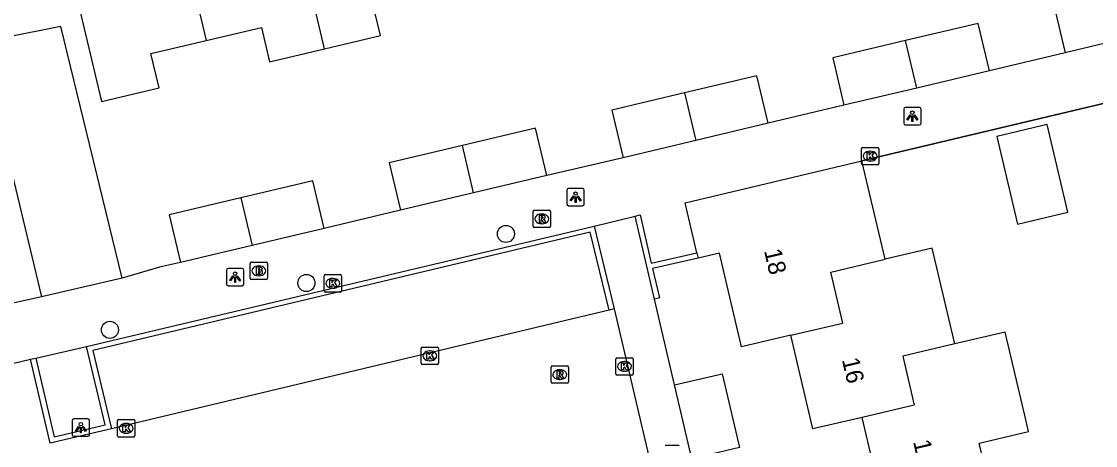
# Model space of a CAD drawing. Extents: x 158038 to 159242, y 380133 to 381214.
# Drawn here: x 158641.1 to 158702.8, y 380611 to 380635.3 of the extents above; entities that cross this region are included whole.
import ezdxf

# ---------------------------------------------------------------- set-up
doc = ezdxf.new("R2010")
doc.units = 0
for name, color, linetype in [('IMGEO_Boom', 7, 'Continuous'), ('IMGEO_Brandkraan', 7, 'Continuous'), ('IMGEO_Hek', 7, 'Continuous'), ('IMGEO_Kolk', 7, 'Continuous'), ('IMGEO_Lichtpunt', 7, 'Continuous'), ('IMGEO_Muur', 7, 'Continuous'), ('IMGEO_Pand', 7, 'Continuous'), ('IMGEO_Pand_nummerreeks', 7, 'Continuous'), ('IMGEO_Parkeervlak_open', 7, 'Continuous'), ('IMGEO_Rijbaan_lokaal_open', 7, 'Continuous'), ('IMGEO_Rioolput', 7, 'Continuous'), ('IMGEO_Voetpad_open', 7, 'Continuous')]:
    doc.layers.add(name, color=color, linetype=linetype)

msp = doc.modelspace()

# ---------------------------------------------------------------- linework, layer by layer
at = {"layer": 'IMGEO_Boom'}
for centre in [(158668.929, 380623.096), (158657.473, 380620.28), (158646.196, 380617.592)]:
    msp.add_circle(centre, 0.489, dxfattribs=at)
at = {"layer": 'IMGEO_Brandkraan'}
for p, q in [((158654.321, 380621.48), (158655.173, 380621.48)), ((158654.246, 380620.554), (158654.246, 380621.406)), ((158654.734, 380621.26), (158654.759, 380621.26)), ((158655.247, 380621.406), (158655.247, 380620.554)), ((158655.173, 380620.48), (158654.321, 380620.48)), ((158654.757, 380620.7), (158654.732, 380620.7))]:
    msp.add_line(p, q, dxfattribs=at)
for points in [[(158654.321, 380621.48), (158655.173, 380621.48)], [(158654.246, 380620.554), (158654.246, 380621.406)], [(158654.594, 380621.18), (158654.594, 380620.78), (158654.807, 380620.78)], [(158654.825, 380621.18), (158654.594, 380621.18)], [(158654.773, 380621.099), (158654.719, 380621.099), (158654.719, 380621.023)], [(158654.719, 380621.023), (158654.772, 380621.023)], [(158654.781, 380620.947), (158654.719, 380620.947), (158654.719, 380620.866)], [(158654.719, 380620.866), (158654.781, 380620.866)], [(158655.247, 380621.406), (158655.247, 380620.554)], [(158655.173, 380620.48), (158654.321, 380620.48)]]:
    msp.add_lwpolyline(points, dxfattribs=at)
for centre, radius, start, end in [((158654.323, 380621.404), 0.0765, 91.55205, 178.44795), ((158654.323, 380621.404), 0.0765, 91.55205, 178.44795), ((158655.171, 380621.404), 0.0765, 1.55205, 88.44795), ((158655.171, 380621.404), 0.0765, 1.55205, 88.44795), ((158654.774, 380621.061), 0.0379, 267.82845, 90.93552), ((158654.782, 380620.906), 0.0404, 269.87594, 90.50774), ((158654.829, 380621.035), 0.145, 59.4692, 91.53667), ((158654.854, 380621.082), 0.0922, 285.51372, 58.15012), ((158654.859, 380620.89), 0.105, 301.31148, 78.98903), ((158654.323, 380620.556), 0.0765, 181.55205, 268.44795), ((158654.323, 380620.556), 0.0765, 181.55205, 268.44795), ((158654.813, 380621.031), 0.251, 268.66757, 293.53466), ((158655.171, 380620.556), 0.0765, 271.55205, 358.44795), ((158655.171, 380620.556), 0.0765, 271.55205, 358.44795)]:
    msp.add_arc(centre, radius, start, end, dxfattribs=at)
for centre, major_axis, ratio, start_param, end_param in [((158654.733, 380620.98), (-0.387, 0.002), 0.722429, 4.712389, 7.853982), ((158654.758, 380620.98), (-0.39, 0.002), 0.717154, 1.570796, 4.712389)]:
    msp.add_ellipse(centre, major_axis=major_axis, ratio=ratio, start_param=start_param, end_param=end_param, dxfattribs=at)
at = {"layer": 'IMGEO_Hek'}
for points in [[(158646.891, 380620.567), (158643.384, 380635.009), (158640.207, 380634.374)], [(158649.038, 380621.183), (158646.891, 380620.567)]]:
    msp.add_lwpolyline(points, dxfattribs=at)
at = {"layer": 'IMGEO_Kolk'}
for p, q in [((158689.338, 380627.14), (158689.338, 380627.992)), ((158689.413, 380628.066), (158690.265, 380628.066)), ((158689.826, 380627.846), (158689.851, 380627.846)), ((158690.339, 380627.992), (158690.339, 380627.14)), ((158690.265, 380627.066), (158689.413, 380627.066)), ((158689.849, 380627.286), (158689.824, 380627.286)), ((158658.495, 380619.833), (158658.495, 380620.685)), ((158658.57, 380620.759), (158659.422, 380620.759)), ((158658.983, 380620.539), (158659.008, 380620.539)), ((158659.496, 380620.685), (158659.496, 380619.833)), ((158659.422, 380619.759), (158658.57, 380619.759)), ((158659.006, 380619.979), (158658.981, 380619.979)), ((158664.06, 380615.673), (158664.06, 380616.525)), ((158664.135, 380616.599), (158664.987, 380616.599)), ((158665.061, 380616.525), (158665.061, 380615.673)), ((158664.548, 380616.379), (158664.573, 380616.379)), ((158675.24, 380615.065), (158675.24, 380615.917)), ((158675.315, 380615.991), (158676.167, 380615.991)), ((158676.241, 380615.917), (158676.241, 380615.065)), ((158664.987, 380615.599), (158664.135, 380615.599)), ((158664.571, 380615.819), (158664.546, 380615.819)), ((158675.728, 380615.771), (158675.753, 380615.771)), ((158676.167, 380614.991), (158675.315, 380614.991)), ((158675.751, 380615.211), (158675.726, 380615.211)), ((158646.624, 380611.512), (158646.624, 380612.364)), ((158646.699, 380612.438), (158647.551, 380612.438)), ((158647.112, 380612.218), (158647.137, 380612.218)), ((158647.625, 380612.364), (158647.625, 380611.512)), ((158647.135, 380611.658), (158647.11, 380611.658)), ((158647.551, 380611.438), (158646.699, 380611.438))]:
    msp.add_line(p, q, dxfattribs=at)
for points in [[(158689.338, 380627.14), (158689.338, 380627.992)], [(158689.413, 380628.066), (158690.265, 380628.066)], [(158689.659, 380627.766), (158689.782, 380627.766), (158689.782, 380627.615), (158689.912, 380627.766), (158690.076, 380627.766), (158689.93, 380627.615), (158690.083, 380627.366), (158689.931, 380627.366), (158689.846, 380627.53), (158689.782, 380627.463), (158689.782, 380627.366), (158689.659, 380627.366), (158689.659, 380627.766)], [(158690.339, 380627.992), (158690.339, 380627.14)], [(158690.265, 380627.066), (158689.413, 380627.066)], [(158658.495, 380619.833), (158658.495, 380620.685)], [(158658.57, 380620.759), (158659.422, 380620.759)], [(158658.816, 380620.459), (158658.939, 380620.459), (158658.939, 380620.308), (158659.069, 380620.459), (158659.233, 380620.459), (158659.087, 380620.308), (158659.24, 380620.059), (158659.088, 380620.059), (158659.003, 380620.223), (158658.939, 380620.156), (158658.939, 380620.059), (158658.816, 380620.059), (158658.816, 380620.459)], [(158659.496, 380620.685), (158659.496, 380619.833)], [(158659.422, 380619.759), (158658.57, 380619.759)], [(158664.06, 380615.673), (158664.06, 380616.525)], [(158664.135, 380616.599), (158664.987, 380616.599)], [(158665.061, 380616.525), (158665.061, 380615.673)], [(158664.381, 380616.299), (158664.504, 380616.299), (158664.504, 380616.148), (158664.634, 380616.299), (158664.798, 380616.299), (158664.652, 380616.148), (158664.805, 380615.899), (158664.653, 380615.899), (158664.568, 380616.063), (158664.504, 380615.996), (158664.504, 380615.899), (158664.381, 380615.899), (158664.381, 380616.299)], [(158675.24, 380615.065), (158675.24, 380615.917)], [(158675.315, 380615.991), (158676.167, 380615.991)], [(158676.241, 380615.917), (158676.241, 380615.065)], [(158664.987, 380615.599), (158664.135, 380615.599)], [(158675.561, 380615.691), (158675.684, 380615.691), (158675.684, 380615.54), (158675.814, 380615.691), (158675.978, 380615.691), (158675.832, 380615.54), (158675.985, 380615.291), (158675.833, 380615.291), (158675.748, 380615.455), (158675.684, 380615.388), (158675.684, 380615.291), (158675.561, 380615.291), (158675.561, 380615.691)], [(158676.167, 380614.991), (158675.315, 380614.991)], [(158646.624, 380611.512), (158646.624, 380612.364)], [(158646.699, 380612.438), (158647.551, 380612.438)], [(158647.625, 380612.364), (158647.625, 380611.512)], [(158646.945, 380612.138), (158647.068, 380612.138), (158647.068, 380611.987), (158647.198, 380612.138), (158647.362, 380612.138), (158647.216, 380611.987), (158647.369, 380611.738), (158647.217, 380611.738), (158647.132, 380611.902), (158647.068, 380611.835), (158647.068, 380611.738), (158646.945, 380611.738), (158646.945, 380612.138)], [(158647.551, 380611.438), (158646.699, 380611.438)]]:
    msp.add_lwpolyline(points, dxfattribs=at)
for centre, start, end in [((158689.415, 380627.99), 91.55205, 178.44795), ((158689.415, 380627.99), 91.55205, 178.44795), ((158690.263, 380627.99), 1.55205, 88.44795), ((158690.263, 380627.99), 1.55205, 88.44795), ((158689.415, 380627.142), 181.55205, 268.44795), ((158689.415, 380627.142), 181.55205, 268.44795), ((158690.263, 380627.142), 271.55205, 358.44795), ((158690.263, 380627.142), 271.55205, 358.44795), ((158658.572, 380620.683), 91.55205, 178.44795), ((158658.572, 380620.683), 91.55205, 178.44795), ((158659.42, 380620.683), 1.55205, 88.44795), ((158659.42, 380620.683), 1.55205, 88.44795), ((158658.572, 380619.835), 181.55205, 268.44795), ((158658.572, 380619.835), 181.55205, 268.44795), ((158659.42, 380619.835), 271.55205, 358.44795), ((158659.42, 380619.835), 271.55205, 358.44795), ((158664.137, 380616.523), 91.55205, 178.44795), ((158664.137, 380616.523), 91.55205, 178.44795), ((158664.985, 380616.523), 1.55205, 88.44795), ((158664.985, 380616.523), 1.55205, 88.44795), ((158675.317, 380615.915), 91.55205, 178.44795), ((158675.317, 380615.915), 91.55205, 178.44795), ((158676.165, 380615.915), 1.55205, 88.44795), ((158676.165, 380615.915), 1.55205, 88.44795), ((158664.137, 380615.675), 181.55205, 268.44795), ((158664.137, 380615.675), 181.55205, 268.44795), ((158664.985, 380615.675), 271.55205, 358.44795), ((158664.985, 380615.675), 271.55205, 358.44795), ((158675.317, 380615.067), 181.55205, 268.44795), ((158675.317, 380615.067), 181.55205, 268.44795), ((158676.165, 380615.067), 271.55205, 358.44795), ((158676.165, 380615.067), 271.55205, 358.44795), ((158646.701, 380612.362), 91.55205, 178.44795), ((158646.701, 380612.362), 91.55205, 178.44795), ((158647.549, 380612.362), 1.55205, 88.44795), ((158647.549, 380612.362), 1.55205, 88.44795), ((158646.701, 380611.514), 181.55205, 268.44795), ((158646.701, 380611.514), 181.55205, 268.44795), ((158647.549, 380611.514), 271.55205, 358.44795), ((158647.549, 380611.514), 271.55205, 358.44795)]:
    msp.add_arc(centre, 0.0765, start, end, dxfattribs=at)
for centre, major_axis, ratio, start_param, end_param in [((158689.825, 380627.566), (-0.387, 0.002), 0.722429, 4.712389, 7.853982), ((158689.85, 380627.566), (-0.39, 0.002), 0.717154, 1.570796, 4.712389), ((158658.982, 380620.259), (-0.387, 0.002), 0.722429, 4.712389, 7.853982), ((158659.007, 380620.259), (-0.39, 0.002), 0.717154, 1.570796, 4.712389), ((158664.547, 380616.099), (-0.387, 0.002), 0.722429, 4.712389, 7.853982), ((158664.572, 380616.099), (-0.39, 0.002), 0.717154, 1.570796, 4.712389), ((158675.727, 380615.491), (-0.387, 0.002), 0.722429, 4.712389, 7.853982), ((158675.752, 380615.491), (-0.39, 0.002), 0.717154, 1.570796, 4.712389), ((158647.111, 380611.938), (-0.387, 0.002), 0.722429, 4.712389, 7.853982), ((158647.136, 380611.938), (-0.39, 0.002), 0.717154, 1.570796, 4.712389)]:
    msp.add_ellipse(centre, major_axis=major_axis, ratio=ratio, start_param=start_param, end_param=end_param, dxfattribs=at)
at = {"layer": 'IMGEO_Lichtpunt'}
for p, q in [((158691.765, 380630.263), (158691.765, 380629.456)), ((158691.765, 380630.263), (158691.765, 380629.456)), ((158692.667, 380630.358), (158691.859, 380630.358)), ((158692.667, 380630.358), (158691.859, 380630.358)), ((158692.761, 380629.456), (158692.761, 380630.263)), ((158692.761, 380629.456), (158692.761, 380630.263)), ((158691.859, 380629.362), (158692.667, 380629.362)), ((158691.859, 380629.362), (158692.667, 380629.362)), ((158672.43, 380625.615), (158672.43, 380624.808)), ((158672.43, 380625.615), (158672.43, 380624.808)), ((158673.332, 380625.71), (158672.524, 380625.71)), ((158673.332, 380625.71), (158672.524, 380625.71)), ((158673.426, 380624.808), (158673.426, 380625.615)), ((158673.426, 380624.808), (158673.426, 380625.615)), ((158672.524, 380624.714), (158673.332, 380624.714)), ((158672.524, 380624.714), (158673.332, 380624.714)), ((158652.883, 380621.022), (158652.883, 380620.215)), ((158652.883, 380621.022), (158652.883, 380620.215)), ((158653.785, 380621.117), (158652.977, 380621.117)), ((158653.785, 380621.117), (158652.977, 380621.117)), ((158653.879, 380620.215), (158653.879, 380621.022)), ((158653.879, 380620.215), (158653.879, 380621.022)), ((158652.977, 380620.121), (158653.785, 380620.121)), ((158652.977, 380620.121), (158653.785, 380620.121)), ((158644.026, 380612.38), (158644.026, 380611.573)), ((158644.026, 380612.38), (158644.026, 380611.573)), ((158644.928, 380612.475), (158644.12, 380612.475)), ((158644.928, 380612.475), (158644.12, 380612.475)), ((158645.022, 380611.573), (158645.022, 380612.38)), ((158645.022, 380611.573), (158645.022, 380612.38)), ((158644.12, 380611.479), (158644.928, 380611.479)), ((158644.12, 380611.479), (158644.928, 380611.479)), ((158678.881, 380610.95), (158678.073, 380610.95)), ((158678.881, 380610.95), (158678.073, 380610.95))]:
    msp.add_line(p, q, dxfattribs=at)
for points in [[(158692.139, 380629.927), (158692.178, 380629.899), (158691.99, 380629.637), (158691.952, 380629.664), (158692.139, 380629.927)], [(158692.241, 380629.879), (158692.288, 380629.879), (158692.288, 380629.557), (158692.241, 380629.557), (158692.241, 380629.879)], [(158692.351, 380629.899), (158692.389, 380629.926), (158692.576, 380629.664), (158692.537, 380629.636), (158692.351, 380629.899)], [(158672.804, 380625.279), (158672.843, 380625.251), (158672.655, 380624.989), (158672.617, 380625.016), (158672.804, 380625.279)], [(158672.906, 380625.231), (158672.953, 380625.231), (158672.953, 380624.909), (158672.906, 380624.909), (158672.906, 380625.231)], [(158673.016, 380625.251), (158673.054, 380625.278), (158673.241, 380625.016), (158673.202, 380624.988), (158673.016, 380625.251)], [(158653.257, 380620.686), (158653.296, 380620.658), (158653.108, 380620.396), (158653.07, 380620.423), (158653.257, 380620.686)], [(158653.359, 380620.638), (158653.406, 380620.638), (158653.406, 380620.316), (158653.359, 380620.316), (158653.359, 380620.638)], [(158653.469, 380620.658), (158653.507, 380620.685), (158653.694, 380620.423), (158653.655, 380620.395), (158653.469, 380620.658)], [(158644.4, 380612.044), (158644.439, 380612.016), (158644.251, 380611.754), (158644.213, 380611.781), (158644.4, 380612.044)], [(158644.502, 380611.996), (158644.549, 380611.996), (158644.549, 380611.674), (158644.502, 380611.674), (158644.502, 380611.996)], [(158644.612, 380612.016), (158644.65, 380612.043), (158644.837, 380611.781), (158644.798, 380611.753), (158644.612, 380612.016)]]:
    msp.add_lwpolyline(points, dxfattribs=at)
for centre in [(158692.264, 380630.061), (158672.929, 380625.413), (158653.382, 380620.82), (158644.525, 380612.178)]:
    msp.add_circle(centre, 0.0994, dxfattribs=at)
for centre, start, end in [((158691.859, 380630.263), 90, 180), ((158691.859, 380630.263), 90, 180), ((158692.667, 380630.263), 0, 90), ((158692.667, 380630.263), 0, 90), ((158691.859, 380629.456), 180, 270), ((158691.859, 380629.456), 180, 270), ((158692.667, 380629.456), 270, 0), ((158692.667, 380629.456), 270, 360), ((158672.524, 380625.615), 90, 180), ((158672.524, 380625.615), 90, 180), ((158673.332, 380625.615), 0, 90), ((158673.332, 380625.615), 0, 90), ((158672.524, 380624.808), 180, 270), ((158672.524, 380624.808), 180, 270), ((158673.332, 380624.808), 270, 0), ((158673.332, 380624.808), 270, 360), ((158652.977, 380621.022), 90, 180), ((158652.977, 380621.022), 90, 180), ((158653.785, 380621.022), 0, 90), ((158653.785, 380621.022), 0, 90), ((158652.977, 380620.215), 180, 270), ((158652.977, 380620.215), 180, 270), ((158653.785, 380620.215), 270, 0), ((158653.785, 380620.215), 270, 360), ((158644.12, 380612.38), 90, 180), ((158644.12, 380612.38), 90, 180), ((158644.928, 380612.38), 0, 90), ((158644.928, 380612.38), 0, 90), ((158644.12, 380611.573), 180, 270), ((158644.12, 380611.573), 180, 270), ((158644.928, 380611.573), 270, 0), ((158644.928, 380611.573), 270, 360)]:
    msp.add_arc(centre, 0.0946, start, end, dxfattribs=at)
at = {"layer": 'IMGEO_Muur'}
for points in [[(158709.509, 380632.073), (158689.357, 380627.287)], [(158676.34, 380624.116), (158676.63, 380624.189), (158677.271, 380621.422), (158679.889, 380622.011)], [(158677.453, 380619.361), (158676.34, 380624.116)], [(158644.849, 380616.63), (158673.995, 380623.552)], [(158673.995, 380623.552), (158675.144, 380618.798)], [(158674.853, 380618.727), (158673.774, 380623.19), (158645.211, 380616.407), (158646.289, 380611.903)], [(158679.96, 380621.708), (158677.346, 380621.12), (158677.745, 380619.429), (158677.453, 380619.361)], [(158675.144, 380618.798), (158674.853, 380618.727)], [(158641.936, 380615.971), (158642.999, 380611.446), (158645.924, 380612.137), (158644.849, 380616.63)], [(158641.644, 380615.902), (158641.936, 380615.971)], [(158646.289, 380611.903), (158642.774, 380611.091), (158641.644, 380615.902)]]:
    msp.add_lwpolyline(points, dxfattribs=at)
at = {"layer": 'IMGEO_Pand'}
for points in [[(158649.878, 380641.958), (158645.752, 380640.98), (158646.222, 380638.999), (158643.881, 380638.444), (158645.717, 380630.694), (158649.021, 380631.477), (158648.553, 380633.45), (158651.711, 380634.198)], [(158649.878, 380641.958), (158651.711, 380634.198)], [(158658.522, 380633.724), (158656.695, 380641.451)], [(158658.522, 380633.724), (158661.726, 380634.483), (158661.256, 380636.467), (158664.395, 380637.211)], [(158705.341, 380634.52), (158704.695, 380637.244), (158700.391, 380636.223), (158701.037, 380633.499)], [(158696.687, 380632.459), (158696.043, 380635.184), (158691.868, 380634.198)], [(158651.711, 380634.198), (158654.897, 380634.953), (158655.366, 380632.976), (158658.522, 380633.724)], [(158705.341, 380634.52), (158701.037, 380633.499)], [(158691.868, 380634.198), (158687.692, 380633.211), (158688.336, 380630.486)], [(158692.511, 380631.473), (158691.868, 380634.198)], [(158683.991, 380629.458), (158683.342, 380632.182), (158679.175, 380631.189)], [(158696.687, 380632.459), (158692.511, 380631.473)], [(158692.511, 380631.473), (158688.336, 380630.486)], [(158679.175, 380631.189), (158675.009, 380630.195), (158675.658, 380627.472)], [(158679.175, 380631.189), (158679.824, 380628.465)], [(158671.273, 380626.443), (158670.63, 380629.168), (158666.432, 380628.177)], [(158683.991, 380629.458), (158679.824, 380628.465)], [(158697.119, 380628.695), (158698.302, 380623.662), (158701.184, 380624.339), (158700.001, 380629.372), (158697.119, 380628.695)], [(158679.824, 380628.465), (158675.658, 380627.472)], [(158666.432, 380628.177), (158662.235, 380627.187), (158662.878, 380624.462)], [(158667.076, 380625.452), (158666.432, 380628.177)], [(158679.889, 380622.011), (158679.216, 380624.879), (158689.357, 380627.287)], [(158690.697, 380621.642), (158689.357, 380627.287)], [(158671.273, 380626.443), (158667.076, 380625.452)], [(158658.489, 380623.417), (158657.846, 380626.142), (158653.719, 380625.164)], [(158653.719, 380625.164), (158649.596, 380624.187), (158650.241, 380621.462)], [(158653.719, 380625.164), (158654.365, 380622.44)], [(158667.076, 380625.452), (158662.878, 380624.462)], [(158658.489, 380623.417), (158654.365, 380622.44)], [(158654.365, 380622.44), (158650.241, 380621.462)], [(158694.695, 380616.786), (158693.404, 380622.278), (158690.697, 380621.642)], [(158679.889, 380622.011), (158679.96, 380621.708)], [(158685.293, 380617.279), (158682.451, 380616.611), (158681.185, 380621.996), (158679.96, 380621.708)], [(158685.293, 380617.279), (158688.263, 380617.977), (158687.574, 380620.908), (158690.697, 380621.642)], [(158689.384, 380612.566), (158686.557, 380611.902), (158685.293, 380617.279)], [(158696.687, 380608.61), (158696.103, 380611.093), (158698.935, 380611.759), (158698.737, 380612.6), (158697.593, 380617.467), (158694.695, 380616.786)], [(158694.695, 380616.786), (158691.709, 380616.084), (158692.37, 380613.267), (158689.384, 380612.566)], [(158678.61, 380614.426), (158681.336, 380615.068), (158682.334, 380610.828), (158679.608, 380610.187)], [(158679.608, 380610.187), (158678.61, 380614.426)], [(158690.646, 380607.197), (158689.384, 380612.566)]]:
    msp.add_lwpolyline(points, dxfattribs=at)
at = {"layer": 'IMGEO_Parkeervlak_open'}
msp.add_lwpolyline([(158646.891, 380620.567), (158643.384, 380635.009), (158640.207, 380634.374)], dxfattribs=at)
at = {"layer": 'IMGEO_Rijbaan_lokaal_open'}
for points in [[(158638.772, 380634.056), (158642.259, 380619.492)], [(158642.259, 380619.492), (158634.865, 380617.848)], [(158674.853, 380618.727), (158646.289, 380611.903)], [(158675.144, 380618.798), (158687.531, 380566.04)], [(158637.085, 380614.819), (158641.644, 380615.902)]]:
    msp.add_lwpolyline(points, dxfattribs=at)
at = {"layer": 'IMGEO_Rioolput'}
for p, q in [((158670.493, 380623.536), (158670.493, 380624.388)), ((158670.568, 380624.462), (158671.42, 380624.462)), ((158670.981, 380624.242), (158671.006, 380624.242)), ((158671.494, 380624.388), (158671.494, 380623.536)), ((158671.42, 380623.462), (158670.568, 380623.462)), ((158671.004, 380623.682), (158670.979, 380623.682)), ((158671.519, 380614.597), (158671.519, 380615.449)), ((158671.594, 380615.523), (158672.446, 380615.523)), ((158672.007, 380615.303), (158672.032, 380615.303)), ((158672.52, 380615.449), (158672.52, 380614.597)), ((158672.03, 380614.743), (158672.005, 380614.743)), ((158672.446, 380614.523), (158671.594, 380614.523))]:
    msp.add_line(p, q, dxfattribs=at)
for points in [[(158670.493, 380623.536), (158670.493, 380624.388)], [(158670.568, 380624.462), (158671.42, 380624.462)], [(158671.082, 380624.16), (158670.83, 380624.162), (158670.83, 380623.762)], [(158670.83, 380623.762), (158670.954, 380623.762), (158670.954, 380623.924), (158670.965, 380623.924)], [(158671.008, 380624.081), (158670.954, 380624.081), (158670.954, 380624)], [(158670.954, 380624), (158671.006, 380624)], [(158671.494, 380624.388), (158671.494, 380623.536)], [(158671.42, 380623.462), (158670.568, 380623.462)], [(158671.012, 380623.895), (158671.083, 380623.762), (158671.223, 380623.762), (158671.158, 380623.888)], [(158671.519, 380614.597), (158671.519, 380615.449)], [(158671.594, 380615.523), (158672.446, 380615.523)], [(158672.52, 380615.449), (158672.52, 380614.597)], [(158672.108, 380615.221), (158671.856, 380615.223), (158671.856, 380614.823)], [(158671.856, 380614.823), (158671.98, 380614.823), (158671.98, 380614.985), (158671.991, 380614.985)], [(158672.034, 380615.142), (158671.98, 380615.142), (158671.98, 380615.061)], [(158671.98, 380615.061), (158672.032, 380615.061)], [(158672.038, 380614.956), (158672.109, 380614.823), (158672.249, 380614.823), (158672.184, 380614.949)], [(158672.446, 380614.523), (158671.594, 380614.523)]]:
    msp.add_lwpolyline(points, dxfattribs=at)
for centre, radius, start, end in [((158670.57, 380624.386), 0.0765, 91.55205, 178.44795), ((158670.57, 380624.386), 0.0765, 91.55205, 178.44795), ((158670.964, 380623.871), 0.0533, 26.02933, 88.69889), ((158670.99, 380624.189), 0.19, 274.7715, 282.96867), ((158671.014, 380623.985), 0.0964, 77.00612, 93.18647), ((158671.028, 380624.042), 0.0378, 276.66336, 79.67722), ((158671.081, 380624.05), 0.109, 350.36119, 89.41601), ((158671.079, 380624.05), 0.112, 277.58423, 350.98172), ((158671.063, 380623.835), 0.108, 29.51342, 73.79051), ((158671.418, 380624.386), 0.0765, 1.55205, 88.44795), ((158671.418, 380624.386), 0.0765, 1.55205, 88.44795), ((158670.57, 380623.538), 0.0765, 181.55205, 268.44795), ((158670.57, 380623.538), 0.0765, 181.55205, 268.44795), ((158671.418, 380623.538), 0.0765, 271.55205, 358.44795), ((158671.418, 380623.538), 0.0765, 271.55205, 358.44795), ((158671.596, 380615.447), 0.0765, 91.55205, 178.44795), ((158671.596, 380615.447), 0.0765, 91.55205, 178.44795), ((158672.444, 380615.447), 0.0765, 1.55205, 88.44795), ((158672.444, 380615.447), 0.0765, 1.55205, 88.44795), ((158671.99, 380614.932), 0.0533, 26.02933, 88.69889), ((158672.016, 380615.25), 0.19, 274.7715, 282.96867), ((158672.04, 380615.046), 0.0964, 77.00612, 93.18647), ((158672.054, 380615.103), 0.0378, 276.66336, 79.67722), ((158672.107, 380615.111), 0.109, 350.36119, 89.41601), ((158672.105, 380615.111), 0.112, 277.58423, 350.98172), ((158672.089, 380614.896), 0.108, 29.51342, 73.79051), ((158671.596, 380614.599), 0.0765, 181.55205, 268.44795), ((158671.596, 380614.599), 0.0765, 181.55205, 268.44795), ((158672.444, 380614.599), 0.0765, 271.55205, 358.44795), ((158672.444, 380614.599), 0.0765, 271.55205, 358.44795)]:
    msp.add_arc(centre, radius, start, end, dxfattribs=at)
for centre, major_axis, ratio, start_param, end_param in [((158670.98, 380623.962), (-0.387, 0.002), 0.722429, 4.712389, 7.853982), ((158671.005, 380623.962), (-0.39, 0.002), 0.717154, 1.570796, 4.712389), ((158672.006, 380615.023), (-0.387, 0.002), 0.722429, 4.712389, 7.853982), ((158672.031, 380615.023), (-0.39, 0.002), 0.717154, 1.570796, 4.712389)]:
    msp.add_ellipse(centre, major_axis=major_axis, ratio=ratio, start_param=start_param, end_param=end_param, dxfattribs=at)
at = {"layer": 'IMGEO_Voetpad_open'}
for points in [[(158701.037, 380633.499), (158696.687, 380632.459)], [(158689.357, 380627.287), (158709.509, 380632.073)], [(158688.336, 380630.486), (158683.991, 380629.458)], [(158675.658, 380627.472), (158671.273, 380626.443)], [(158662.878, 380624.462), (158658.489, 380623.417)], [(158673.995, 380623.552), (158676.34, 380624.116)], [(158650.241, 380621.462), (158649.038, 380621.183), (158646.891, 380620.567)], [(158646.891, 380620.567), (158642.259, 380619.492)], [(158678.61, 380614.426), (158677.453, 380619.361)], [(158641.936, 380615.971), (158644.849, 380616.63)]]:
    msp.add_lwpolyline(points, dxfattribs=at)

# ---------------------------------------------------------------- texts
at = {"layer": 'IMGEO_Pand_nummerreeks'}
for s, rotation, p in [('18', 283.22498, (158683.743, 380622.131)), ('16', 283.22864, (158688.21, 380615.883)), ('14', 283.22743, (158692.3, 380611.174))]:
    msp.add_text(s, height=1, rotation=rotation, dxfattribs=at).set_placement(p)

doc.saveas('drawing.dxf')
